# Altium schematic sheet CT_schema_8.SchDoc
size 147 x 119 mm
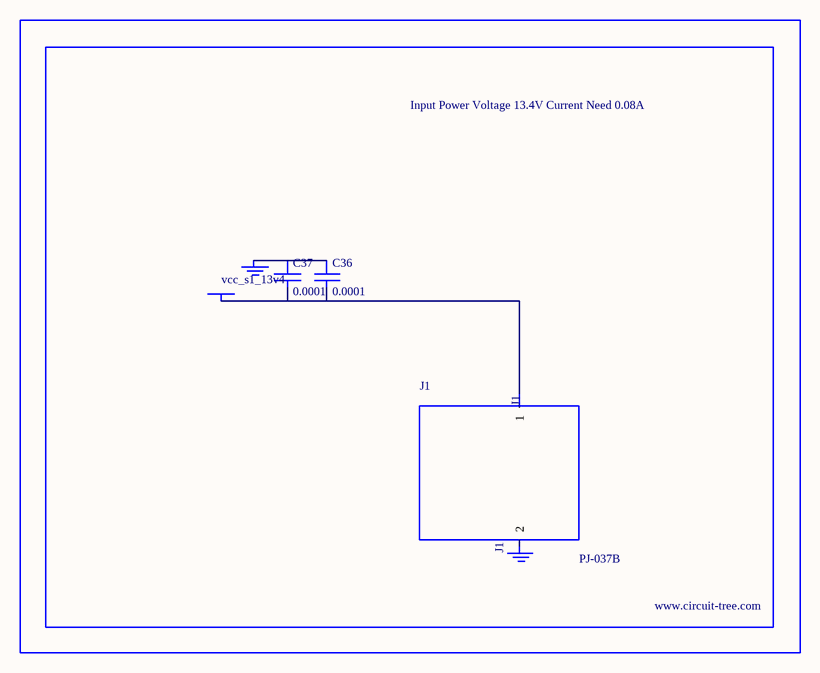
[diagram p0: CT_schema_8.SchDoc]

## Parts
BORDER7  (no value)
C36  0.0001  [EXV-9H]
C37  0.0001  [EXV-9H]
GND_INSTANCE_7_0  (no value)
GND_INSTANCE_7_1  (no value)
J1  PJ-037B  [PJ-037B_PACKAGE]
POWER_INSTANCE_7_0  vcc_s1_13v4

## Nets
NetC36_1: C36.1 C37.1 GND_INSTANCE_7_0.0(GND)
NetC36_2: C36.2 C37.2 J1.1 POWER_INSTANCE_7_0.0(PWR)

Not connected (* = marked no-connect by the designer): GND_INSTANCE_7_1 0(GND); J1 2

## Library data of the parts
BORDER7 = BORDER_PAGE7
C36 C37 = EDK107M035A9HAA
GND_INSTANCE_7_0 GND_INSTANCE_7_1 = GND
POWER_INSTANCE_7_0 = PWR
